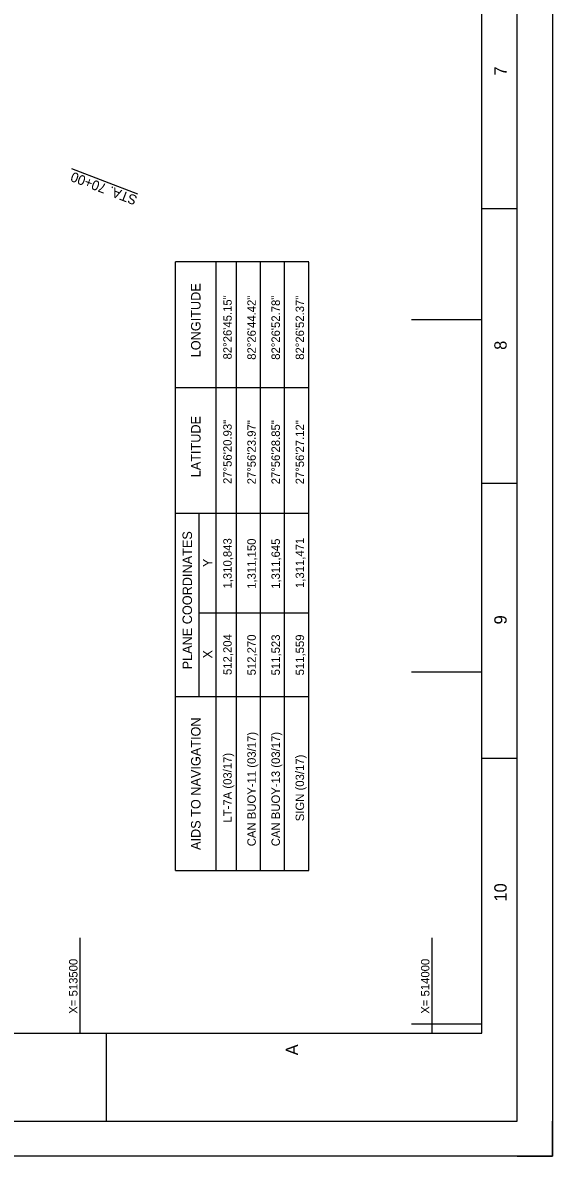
# Model space of a CAD drawing. Extents: x 510771 to 514171, y 1309813 to 1314213.
# Drawn here: x 513418 to 514171, y 1309813 to 1311422 of the extents above; entities that cross this region are included whole.
import ezdxf

# ---------------------------------------------------------------- set-up
doc = ezdxf.new("R2010")
doc.units = 0
for name, color, linetype in [('G-ANNO-NPLT', 7, 'Continuous'), ('G-ANNO-TTLB', 7, 'Continuous'), ('V-ALGN-TEXT', 7, 'Continuous'), ('V-ANNO-SCHD', 7, 'Continuous'), ('V-ANNO-SYMB', 7, 'Continuous'), ('V-TOPO-COOR-STAT', 7, 'Continuous')]:
    doc.layers.add(name, color=color, linetype=linetype)

msp = doc.modelspace()

# ---------------------------------------------------------------- linework, layer by layer
at = {"layer": 'G-ANNO-NPLT'}
msp.add_lwpolyline([(510770.7, 1309812.6), (510770.7, 1314212.6), (514170.7, 1314212.6), (514170.7, 1309812.6)], close=True, dxfattribs=at)
msp.add_lwpolyline([(514120.7, 1309812.6), (514170.7, 1309812.6), (514170.7, 1309862.6)], dxfattribs=at)
at = {"layer": 'G-ANNO-TTLB'}
for p, q in [((514120.7, 1311157.6), (514070.7, 1311157.6)), ((514120.7, 1310767.6), (514070.7, 1310767.6)), ((514120.7, 1310377.6), (514070.7, 1310377.6)), ((513537.4, 1309862.6), (513537.4, 1309987.6))]:
    msp.add_line(p, q, dxfattribs=at)
for points in [[(514120.7, 1309862.6), (514120.7, 1314162.6), (510820.7, 1314162.6), (510820.7, 1309862.6)], [(510870.7, 1314112.6), (510870.7, 1309987.6), (514070.7, 1309987.6), (514070.7, 1314112.6)]]:
    msp.add_lwpolyline(points, close=True, dxfattribs=at)
at = {"layer": 'V-ALGN-TEXT'}
msp.add_line((513581.5, 1311178.7), (513488.1, 1311214.3), dxfattribs=at)
at = {"layer": 'V-ANNO-SCHD'}
for p, q in [((513635.2, 1310218.5), (513635.2, 1311082.6)), ((513824.6, 1311082.6), (513635.2, 1311082.6)), ((513692.9, 1310218.5), (513692.9, 1311082.6)), ((513721.8, 1310218.5), (513721.8, 1311082.6)), ((513756, 1310218.5), (513756, 1311082.1)), ((513790.3, 1310218.5), (513790.3, 1311082.1)), ((513824.6, 1310218.5), (513824.6, 1311082.1)), ((513635.2, 1310904.2), (513824.6, 1310904.2)), ((513635.2, 1310725.9), (513824.6, 1310725.9)), ((513668.9, 1310465.2), (513668.9, 1310725.9)), ((513668.9, 1310584.1), (513824.6, 1310584.1)), ((513635.2, 1310465.2), (513824.6, 1310465.2)), ((513635.2, 1310218.5), (513824.6, 1310218.5))]:
    msp.add_line(p, q, dxfattribs=at)
at = {"layer": 'V-TOPO-COOR-STAT'}
for p, q in [((514070.7, 1311000), (513970.7, 1311000)), ((514070.7, 1310500), (513970.7, 1310500)), ((513500, 1309987.6), (513500, 1310122.6)), ((514000, 1309987.6), (514000, 1310122.6)), ((514070.7, 1310000), (513970.7, 1310000))]:
    msp.add_line(p, q, dxfattribs=at)

# ---------------------------------------------------------------- texts
at = {"layer": 'G-ANNO-TTLB'}
for s, p in [('7', (514105.7, 1311346.9)), ('8', (514105.7, 1310957.5)), ('9', (514105.7, 1310567.7)), ('10', (514105.7, 1310174.2)), ('A', (513809.5, 1309956))]:
    msp.add_text(s, height=17.5, rotation=90, dxfattribs=at).set_placement(p)
at = {"layer": 'V-ALGN-TEXT'}
msp.add_text('STA. 70+00', height=13.92, rotation=159.1799, dxfattribs=at).set_placement((513582.1, 1311175.5))
at = {"layer": 'V-ANNO-SCHD'}
for s, height, p in [('LONGITUDE', 13.47, (513670.8, 1310947)), ('LATITUDE', 13.47, (513670.8, 1310776.6)), ('PLANE COORDINATES', 13.471, (513658.7, 1310503.9)), ('Y', 13.5, (513687.6, 1310649.1)), ('X', 13.5, (513687.6, 1310519.3)), ('AIDS TO NAVIGATION', 13.471, (513670.8, 1310247.5))]:
    msp.add_text(s, height=height, rotation=90.0001, dxfattribs=at).set_placement(p)
at = {"layer": 'V-ANNO-SYMB'}
for s, p in [('82%%D26\'45.15"', (513715.1, 1310943.9)), ('82%%D26\'44.42"', (513749.3, 1310943.4)), ('82%%D26\'52.78"', (513783.6, 1310943.4)), ('82%%D26\'52.37"', (513817.9, 1310943.4)), ('27%%D56\'20.93"', (513715.1, 1310767.1)), ('27%%D56\'23.97"', (513749.3, 1310766.6)), ('27%%D56\'28.85"', (513783.6, 1310766.6)), ('27%%D56\'27.12"', (513817.9, 1310766.6)), ('1,310,843', (513715.1, 1310618.7)), ('1,311,150', (513749.3, 1310618.2)), ('1,311,645', (513783.6, 1310618.2)), ('1,311,471', (513817.9, 1310619.4)), ('512,204', (513715.1, 1310495.9)), ('512,270', (513749.3, 1310495.4)), ('511,523', (513783.6, 1310495.4)), ('511,559', (513817.9, 1310495.4)), ('CAN BUOY-11 (03/17)', (513749.3, 1310252.8)), ('CAN BUOY-13 (03/17)', (513783.6, 1310252.8)), ('LT-7A (03/17)', (513715.1, 1310286.4)), ('SIGN (03/17)', (513817.9, 1310288.3))]:
    msp.add_text(s, height=12, rotation=90, dxfattribs=at).set_placement(p)
at = {"layer": 'V-TOPO-COOR-STAT'}
for s, p in [('X= 513500', (513496, 1310015)), ('X= 514000', (513996, 1310015))]:
    msp.add_text(s, height=12, rotation=90, dxfattribs=at).set_placement(p)

doc.saveas('drawing.dxf')
